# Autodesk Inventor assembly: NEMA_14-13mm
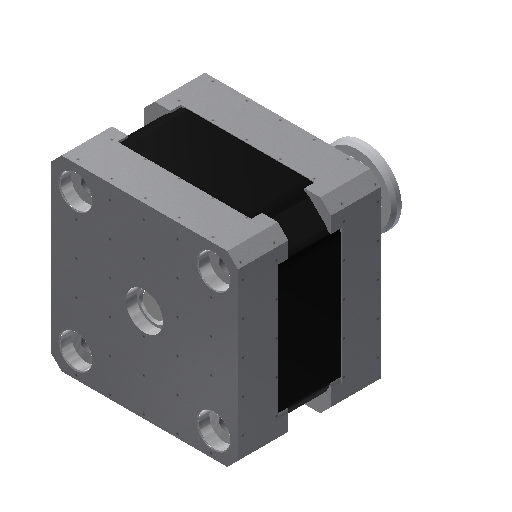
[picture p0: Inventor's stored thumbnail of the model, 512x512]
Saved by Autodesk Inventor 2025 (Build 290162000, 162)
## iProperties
Created: 2019-11
Part Number: NEMA_14-13mm
Material: Générique
Document SubType Name: Assembly
Designer: thoma
Author: thoma
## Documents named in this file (4)
- C:\Users\R5800u\Desktop\nema14\NEMA_14-13mm.iam
- C:\Users\R5800u\Desktop\nema14\NEMA_14HM11-0404S_BODY.ipt
- C:\Users\R5800u\Desktop\nema14\GT2 16 Teeth Free Pulley.ipt
- C:\Users\R5800u\Desktop\nema14\NEMA_14HM11-0404S_SHAFT13.ipt
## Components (3 placed, 3 different names)
1. NEMA_14HM11-0404S:1 — Affleurement:2, Placage:2, Placage:3, Affleurement:3
2. NEMA_14HM11-0404S_SHAFT13:1 — Affleurement:3, Rotazionale:1
3. GT2 16 Teeth Free Pulley:1 — Rotazionale:1
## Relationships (5: Flush 2, Mate 2, RevoluteJoint 1)
- Affleurement:2 [Flush]: NEMA_14HM11-0404S:1
- Placage:2 [Mate]: NEMA_14HM11-0404S:1
- Placage:3 [Mate]: NEMA_14HM11-0404S:1
- Affleurement:3 [Flush]: NEMA_14HM11-0404S:1 ↔ NEMA_14HM11-0404S_SHAFT13:1
- Rotazionale:1 [RevoluteJoint]: NEMA_14HM11-0404S_SHAFT13:1 ↔ GT2 16 Teeth Free Pulley:1
